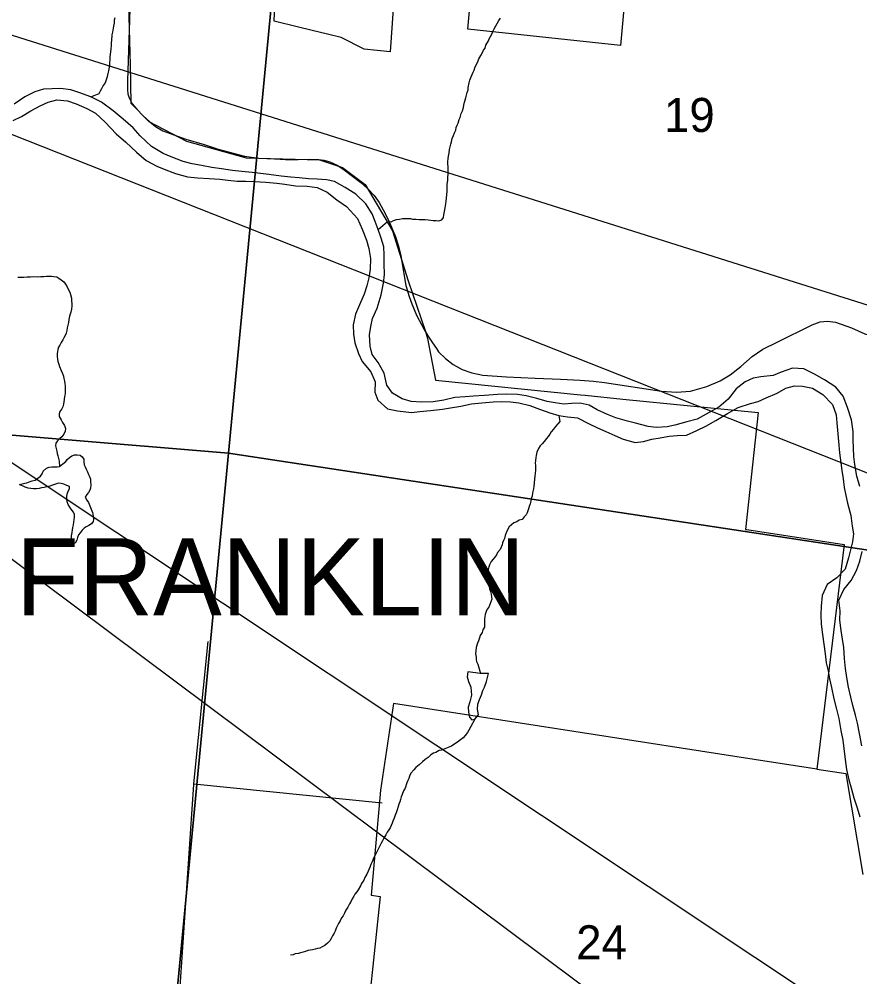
# Model space of a CAD drawing. Extents: x -7.3 to 34, y 0 to 22.
# Drawn here: x 7.321 to 8.354, y 16.227 to 17.405 of the extents above; entities that cross this region are included whole.
import ezdxf

# ---------------------------------------------------------------- set-up
doc = ezdxf.new("R2010")
doc.units = 0
for name, color, linetype in [('GM_X_City_Street', 7, 'Continuous'), ('GM_X_Corporation', 7, 'Continuous'), ('GM_X_Corporation_Text', 7, 'Continuous'), ('GM_X_County_Road', 7, 'Continuous'), ('GM_X_Minor_River', 7, 'Continuous'), ('GM_X_Section_Text', 7, 'Continuous'), ('SH_Text', 7, 'Continuous')]:
    doc.layers.add(name, color=color, linetype=linetype)

msp = doc.modelspace()

# ---------------------------------------------------------------- linework, layer by layer
at = {"layer": 'GM_X_City_Street'}
msp.add_line((7.5353, 16.4644), (7.7668, 16.4414), dxfattribs=at)
msp.add_lwpolyline([(7.515, 16.1606), (7.5352, 16.4637), (7.5353, 16.4644), (7.5529, 16.6394)], dxfattribs=at)
at = {"layer": 'GM_X_Corporation'}
for points in [[(7.6737, 17.8749), (7.5781, 16.8709), (6.5281, 16.9583), (6.6194, 17.9753)], [(8.6893, 17.7371), (8.5942, 16.7168), (7.5781, 16.8709), (7.6737, 17.8749)], [(7.5781, 16.8709), (7.4799, 15.8457), (6.4371, 15.9508), (6.5281, 16.9583)], [(8.5942, 16.7168), (8.4992, 15.7029), (7.4799, 15.8457), (7.5781, 16.8709)]]:
    msp.add_lwpolyline(points, close=True, dxfattribs=at)
for points in [[(8.0931, 17.7385), (8.0598, 17.3723), (7.8722, 17.3924), (7.8829, 17.5093)], [(7.7823, 17.4468), (7.7791, 17.3996), (7.7767, 17.3644), (7.7446, 17.3678), (7.7163, 17.382), (7.6995, 17.3861), (7.6809, 17.3907), (7.6622, 17.3953), (7.6357, 17.4018), (7.634, 17.4022), (7.6362, 17.4532)], [(7.4551, 17.4222), (7.4572, 17.3486), (7.4578, 17.3014), (7.48, 17.279), (7.5265, 17.2546), (7.5995, 17.2342), (7.6897, 17.2318), (7.7181, 17.2223), (7.7461, 17.2012), (7.7794, 17.1442), (7.7987, 17.083), (7.8202, 17.0207), (7.8227, 17.0119), (7.8326, 16.9608), (8.0108, 16.9429), (8.0165, 16.9423), (8.0629, 16.9376), (8.229, 16.921), (8.2137, 16.7774), (8.215, 16.7772), (8.3348, 16.7587), (8.3013, 16.4827), (8.2244, 16.4945), (7.7807, 16.5633), (7.765, 16.4567), (7.7642, 16.4475), (7.7533, 16.3279), (7.7646, 16.3262), (7.7435, 16.1277)], [(7.4551, 17.4222), (7.4572, 17.3486), (7.4578, 17.3014), (7.48, 17.279), (7.5265, 17.2546), (7.5995, 17.2342), (7.6897, 17.2318), (7.7181, 17.2223), (7.7461, 17.2012), (7.7795, 17.1442), (7.7987, 17.083), (7.8202, 17.0207), (7.8227, 17.0119), (7.8326, 16.9608), (8.0108, 16.9429), (8.0165, 16.9423), (8.0629, 16.9376), (8.229, 16.921), (8.2137, 16.7774), (8.215, 16.7772), (8.3348, 16.7587), (8.3013, 16.4827), (8.3368, 16.4772), (8.3577, 16.3531)]]:
    msp.add_lwpolyline(points, dxfattribs=at)
at = {"layer": 'GM_X_County_Road'}
for points in [[(7.4566, 17.4171), (7.4564, 17.4038), (7.4536, 17.3288), (7.4537, 17.3178), (7.454, 17.313), (7.4557, 17.3078), (7.4597, 17.3006), (7.4652, 17.2941), (7.473, 17.2859), (7.4813, 17.2785), (7.4882, 17.2728), (7.4971, 17.2675), (7.5254, 17.2571), (7.5481, 17.2505), (7.5652, 17.2448), (7.5976, 17.2363), (7.6151, 17.2338), (7.6344, 17.2329), (7.6479, 17.2322), (7.6638, 17.2321), (7.6771, 17.2325), (7.6889, 17.2321), (7.6953, 17.2313), (7.7027, 17.2292), (7.7123, 17.2248), (7.7202, 17.2194), (7.7406, 17.2039), (7.7489, 17.1966), (7.7569, 17.1879), (7.763, 17.1791), (7.768, 17.1703), (7.7742, 17.1584), (7.7782, 17.1491), (7.7834, 17.1371), (7.787, 17.1257), (7.7897, 17.1138), (7.796, 17.0772), (7.7999, 17.0638), (7.8032, 17.0548), (7.8091, 17.0409), (7.8184, 17.0232), (7.8232, 17.0153), (7.8288, 17.0069), (7.8336, 16.9997)], [(8.2525, 17.0076), (8.2956, 17.0288), (8.3054, 17.0324), (8.3142, 17.0333), (8.3241, 17.0322), (8.3437, 17.0253), (8.3601, 17.0176), (8.3853, 17.0105), (8.4431, 17.003), (8.4875, 16.9979), (8.5306, 16.9929), (8.5866, 16.9859), (8.594, 16.9857), (8.6023, 16.9868), (8.613, 16.9901), (8.6204, 16.994)], [(7.8336, 16.9997), (7.8363, 16.9958), (7.8448, 16.9875), (7.8541, 16.9799), (7.8652, 16.9738), (7.8773, 16.9697), (7.8905, 16.9669), (7.9197, 16.965), (7.9548, 16.9633), (7.9861, 16.9622), (8.0102, 16.961), (8.0267, 16.9595), (8.04, 16.958), (8.1102, 16.9473), (8.1286, 16.9461), (8.146, 16.9474), (8.1662, 16.9532), (8.1823, 16.96), (8.1947, 16.9673), (8.2077, 16.9777), (8.2217, 16.9898), (8.2349, 16.9989), (8.2525, 17.0076)]]:
    msp.add_lwpolyline(points, dxfattribs=at)
at = {"layer": 'GM_X_Minor_River'}
for points in [[(7.4088, 17.309), (7.4168, 17.3123), (7.4191, 17.3133), (7.4207, 17.3163), (7.4223, 17.3193), (7.4239, 17.3227), (7.4258, 17.3253), (7.427, 17.3279), (7.4278, 17.3306), (7.4291, 17.334), (7.4299, 17.3378), (7.4307, 17.3412), (7.4316, 17.3457), (7.432, 17.3484), (7.4321, 17.3518), (7.4325, 17.3544), (7.4326, 17.3582), (7.4331, 17.3643), (7.4336, 17.3681), (7.4341, 17.3723), (7.4341, 17.3753), (7.4346, 17.3783), (7.4351, 17.3852), (7.4356, 17.3886), (7.4369, 17.3961), (7.4377, 17.3995), (7.4378, 17.4037), (7.4386, 17.4068)], [(7.7618, 17.1462), (7.7734, 17.1558), (7.7779, 17.1555), (7.7806, 17.1572), (7.7844, 17.1582), (7.7882, 17.1589), (7.792, 17.1596), (7.7955, 17.1595), (7.7981, 17.1594), (7.8015, 17.1594), (7.8042, 17.1589), (7.8083, 17.1588), (7.8125, 17.1584), (7.8159, 17.1583), (7.8197, 17.1582), (7.8235, 17.1578), (7.8265, 17.1577), (7.8295, 17.1572), (7.8333, 17.1572), (7.8367, 17.1567), (7.8402, 17.1578), (7.8421, 17.1608), (7.8426, 17.1642), (7.8434, 17.168), (7.8443, 17.1725), (7.8452, 17.1774), (7.8456, 17.1808), (7.8461, 17.1846), (7.8462, 17.1892), (7.8466, 17.1926), (7.8467, 17.1975), (7.8468, 17.2013), (7.8477, 17.2066), (7.8478, 17.2104), (7.8479, 17.2142), (7.8479, 17.2173), (7.848, 17.2203), (7.8481, 17.2234), (7.8477, 17.2264), (7.8478, 17.2294), (7.8479, 17.2332), (7.8483, 17.2363), (7.8492, 17.2397), (7.8496, 17.2442), (7.8513, 17.251), (7.8521, 17.2537), (7.853, 17.2578), (7.8546, 17.2616), (7.8558, 17.265), (7.8574, 17.268), (7.8578, 17.2714), (7.859, 17.2741), (7.8602, 17.2767), (7.8614, 17.2812), (7.8626, 17.2839), (7.8639, 17.2888), (7.8655, 17.2918), (7.8667, 17.2959), (7.8671, 17.299), (7.868, 17.3024), (7.8696, 17.3077), (7.8704, 17.3111), (7.8713, 17.3145), (7.8725, 17.3179), (7.8725, 17.3205), (7.8738, 17.3262), (7.8746, 17.3296), (7.8762, 17.3337), (7.8786, 17.3394), (7.8798, 17.342), (7.8814, 17.3462), (7.8834, 17.3495), (7.885, 17.3533), (7.8858, 17.356), (7.8882, 17.3601), (7.8902, 17.3635), (7.8914, 17.3665), (7.8933, 17.3691), (7.8945, 17.3725), (7.8977, 17.3778), (7.8985, 17.3804), (7.9001, 17.3834), (7.902, 17.3868), (7.9029, 17.3894), (7.9045, 17.3928), (7.9068, 17.3962), (7.9084, 17.3992), (7.9104, 17.4029), (7.9123, 17.4059)], [(7.7608, 17.0494), (7.7658, 17.0659), (7.7684, 17.0799), (7.7698, 17.0909), (7.7694, 17.1038), (7.7693, 17.1149), (7.7688, 17.1247), (7.7657, 17.1355), (7.7618, 17.1462), (7.7583, 17.1558), (7.7547, 17.1654), (7.7467, 17.1777), (7.7345, 17.1894), (7.7214, 17.1977), (7.7084, 17.2049), (7.6986, 17.207), (7.6868, 17.2077), (7.6762, 17.2084), (7.6649, 17.2094), (7.6547, 17.2104), (7.6429, 17.2115), (7.6274, 17.2138), (7.6172, 17.2148), (7.607, 17.2162), (7.5945, 17.2173), (7.5828, 17.2187), (7.5692, 17.2206), (7.5575, 17.2224), (7.5447, 17.2246), (7.5334, 17.2268), (7.5224, 17.2297), (7.5074, 17.2354), (7.4977, 17.2395), (7.4831, 17.2482), (7.4694, 17.2611), (7.4606, 17.2712), (7.4483, 17.2817), (7.4361, 17.2919), (7.4219, 17.3025), (7.4088, 17.309), (7.3938, 17.3143), (7.384, 17.3176), (7.3716, 17.3194), (7.3613, 17.3189), (7.3507, 17.3184), (7.34, 17.3153), (7.3277, 17.3091), (7.3146, 17.2999)], [(7.3133, 17.2802), (7.3233, 17.2849), (7.3348, 17.2918), (7.3464, 17.298), (7.3563, 17.3027), (7.367, 17.3055), (7.3799, 17.3044), (7.3908, 17.3007), (7.4039, 17.2946), (7.4144, 17.2891), (7.4262, 17.2781), (7.4399, 17.2637), (7.4518, 17.2535), (7.4647, 17.2411), (7.4766, 17.2309), (7.49, 17.2237), (7.5009, 17.2193), (7.5126, 17.2148), (7.5276, 17.2106), (7.5397, 17.2095), (7.5541, 17.2088), (7.5674, 17.2077), (7.5772, 17.2067), (7.5885, 17.2056), (7.5992, 17.2054), (7.6098, 17.2051), (7.6238, 17.2044), (7.6374, 17.2029), (7.6472, 17.2019), (7.6604, 17.1996), (7.6745, 17.1993), (7.6869, 17.1978), (7.6993, 17.1918), (7.7112, 17.1824), (7.7231, 17.1741), (7.7367, 17.1594), (7.7421, 17.1463), (7.7474, 17.1329), (7.7506, 17.1225), (7.7525, 17.1103), (7.7522, 17.0971), (7.7504, 17.0865), (7.7482, 17.0766), (7.7449, 17.0665), (7.7401, 17.0563), (7.7341, 17.0421), (7.7311, 17.0288), (7.7315, 17.0174), (7.7331, 17.0068), (7.7377, 16.9937), (7.7424, 16.9837), (7.7531, 16.9709), (7.7581, 16.9587), (7.7577, 16.9461), (7.7616, 16.9362), (7.7735, 16.9256), (7.7856, 16.923), (7.803, 16.9211), (7.8132, 16.9223), (7.8262, 16.9235), (7.841, 16.925), (7.8509, 16.9267), (7.8635, 16.929), (7.8768, 16.9317), (7.8894, 16.9329), (7.9034, 16.9341), (7.9133, 16.9346), (7.9247, 16.9343), (7.9349, 16.9329), (7.9484, 16.9295), (7.9601, 16.9251), (7.9728, 16.9206), (7.9841, 16.9172), (7.9947, 16.9158), (8.0072, 16.9144), (8.0207, 16.9076), (8.0315, 16.9024), (8.042, 16.8976), (8.0529, 16.8927), (8.063, 16.8883), (8.0777, 16.8841), (8.0883, 16.8854), (8.0983, 16.8882), (8.1085, 16.8898), (8.1196, 16.8918), (8.1295, 16.8927), (8.1409, 16.8932), (8.1539, 16.8989), (8.1647, 16.9043), (8.177, 16.9112), (8.1916, 16.92), (8.2047, 16.9273)], [(7.319, 17.0874), (7.322, 17.0873), (7.3262, 17.0876), (7.3304, 17.0879), (7.3346, 17.0878), (7.3388, 17.0881), (7.3429, 17.088), (7.3471, 17.0883), (7.3509, 17.0882), (7.3543, 17.0885), (7.3577, 17.0888), (7.3604, 17.0888), (7.3634, 17.0883), (7.3668, 17.0879), (7.3694, 17.0863), (7.3724, 17.084), (7.3754, 17.0816), (7.3776, 17.0789), (7.3794, 17.0754), (7.3809, 17.0727), (7.3827, 17.0689), (7.3838, 17.0662), (7.3848, 17.0616), (7.3851, 17.0582), (7.3854, 17.0548), (7.3854, 17.0521), (7.3849, 17.048), (7.3841, 17.0446), (7.3833, 17.0419), (7.3825, 17.0393), (7.3816, 17.0355), (7.3811, 17.0317), (7.3803, 17.0283), (7.3795, 17.0253), (7.379, 17.0219), (7.3782, 17.0185), (7.377, 17.0158), (7.3754, 17.0128), (7.3742, 17.0102), (7.3723, 17.0072), (7.3707, 17.0038), (7.3691, 17.0012), (7.3683, 16.9985), (7.3679, 16.9959), (7.3674, 16.9932), (7.3673, 16.9898), (7.3677, 16.9868), (7.3683, 16.9837), (7.3694, 16.9803), (7.3701, 16.9776), (7.3723, 16.9726), (7.3737, 16.9691), (7.3752, 16.9657), (7.3755, 16.963), (7.3765, 16.9596), (7.3769, 16.9569), (7.3772, 16.9535), (7.3771, 16.9501), (7.377, 16.9467), (7.377, 16.944), (7.3765, 16.9406), (7.3761, 16.9372), (7.3756, 16.9341), (7.3752, 16.9315)], [(8.3542, 16.8301), (8.3504, 16.8427), (8.3481, 16.8572), (8.3469, 16.8671), (8.3464, 16.8774), (8.3459, 16.8876), (8.3458, 16.8979), (8.3439, 16.912), (8.3389, 16.9273), (8.3336, 16.9411), (8.3244, 16.9523), (8.3106, 16.9614), (8.2983, 16.9682), (8.2852, 16.9746), (8.2712, 16.9757), (8.2574, 16.9707), (8.2474, 16.9664), (8.2326, 16.9649), (8.2231, 16.9632), (8.2131, 16.9589), (8.2019, 16.9501), (8.1921, 16.9374), (8.1808, 16.9275), (8.1689, 16.9209), (8.1543, 16.913), (8.1413, 16.9095), (8.1268, 16.9053), (8.1172, 16.9036), (8.1039, 16.9025), (8.0937, 16.9039), (8.0783, 16.908), (8.0685, 16.9106), (8.0542, 16.9147), (8.0437, 16.9184), (8.0313, 16.9244), (8.0212, 16.93), (8.0103, 16.9325), (7.9997, 16.932), (7.9902, 16.9315), (7.9796, 16.9329), (7.9698, 16.9347), (7.957, 16.9381), (7.9438, 16.9414), (7.9332, 16.9432), (7.9203, 16.9435), (7.9086, 16.9431), (7.8926, 16.942), (7.879, 16.9412), (7.8687, 16.9403), (7.8562, 16.9395), (7.8428, 16.9364), (7.8295, 16.9341), (7.8154, 16.9337), (7.8026, 16.9347), (7.7916, 16.9377), (7.7797, 16.9448), (7.7727, 16.9545), (7.7693, 16.9694), (7.7621, 16.9825), (7.7544, 16.9925), (7.752, 17.0025), (7.7512, 17.0166), (7.753, 17.0268), (7.7548, 17.0366), (7.7608, 17.0494)], [(8.2047, 16.9273), (8.2196, 16.9322), (8.2292, 16.9346), (8.2391, 16.9389), (8.2526, 16.945), (8.263, 16.9509), (8.2737, 16.954), (8.2835, 16.9534), (8.2959, 16.9508), (8.3086, 16.9432), (8.3205, 16.9308), (8.3251, 16.9181), (8.3259, 16.9082), (8.3271, 16.8949), (8.328, 16.8854), (8.3291, 16.8713), (8.3307, 16.8591), (8.332, 16.8496), (8.3336, 16.8397), (8.3349, 16.829), (8.3369, 16.8191), (8.3389, 16.8096), (8.3431, 16.7946), (8.3446, 16.7813), (8.3463, 16.7718), (8.3452, 16.7619), (8.3427, 16.7521), (8.3402, 16.7423), (8.336, 16.7284), (8.3259, 16.718), (8.3139, 16.7096), (8.3079, 16.696), (8.3064, 16.6828), (8.3061, 16.6725), (8.3066, 16.6608), (8.3082, 16.6482), (8.3097, 16.6364), (8.3113, 16.6242), (8.3129, 16.6135), (8.315, 16.6036), (8.317, 16.5937), (8.3193, 16.583), (8.322, 16.5692), (8.3255, 16.5562), (8.3282, 16.5448), (8.3309, 16.5303), (8.3332, 16.5181), (8.3345, 16.5082), (8.336, 16.4945), (8.3379, 16.4823), (8.3406, 16.4693), (8.3434, 16.4597), (8.3469, 16.4475), (8.3507, 16.4349), (8.3542, 16.4238)], [(7.3752, 16.9315), (7.3743, 16.9281), (7.3731, 16.9255), (7.3704, 16.9221), (7.3696, 16.9195), (7.3699, 16.916), (7.3721, 16.9122), (7.3739, 16.9087), (7.3765, 16.9052), (7.3776, 16.9014), (7.3771, 16.898), (7.3755, 16.8946), (7.3732, 16.8913), (7.3705, 16.889), (7.3677, 16.8864), (7.3658, 16.8834), (7.3653, 16.88), (7.366, 16.8766), (7.3667, 16.8735), (7.3674, 16.8705), (7.3681, 16.8678), (7.3688, 16.8644), (7.3699, 16.8613), (7.3701, 16.8545)], [(7.9841, 16.9172), (7.9854, 16.9102), (7.9827, 16.9073), (7.9799, 16.9039), (7.9776, 16.9005), (7.9748, 16.8972), (7.9729, 16.8945), (7.9709, 16.8915), (7.969, 16.8889), (7.9659, 16.8856), (7.9635, 16.8826), (7.9612, 16.88), (7.9592, 16.8766), (7.9569, 16.8725), (7.956, 16.8683), (7.9556, 16.8657), (7.9555, 16.8622), (7.9551, 16.8588), (7.9554, 16.8562), (7.9553, 16.8527), (7.9552, 16.8497), (7.9548, 16.8463), (7.9547, 16.8425), (7.9542, 16.8395), (7.9538, 16.8342), (7.9533, 16.8307), (7.9528, 16.8273), (7.9516, 16.8224), (7.9511, 16.8183), (7.9499, 16.8152), (7.9495, 16.8122), (7.9487, 16.8088), (7.9474, 16.8054), (7.9466, 16.8028), (7.945, 16.7979), (7.9438, 16.7952), (7.9415, 16.7926), (7.9388, 16.7896), (7.9353, 16.7886), (7.9326, 16.7867), (7.9288, 16.7853), (7.9257, 16.7831), (7.923, 16.7805), (7.9206, 16.776), (7.9194, 16.7733), (7.9182, 16.77), (7.9174, 16.7662), (7.9162, 16.7635), (7.915, 16.7609), (7.9142, 16.7583), (7.913, 16.7556), (7.9118, 16.7526), (7.9087, 16.7489), (7.9075, 16.7462), (7.9055, 16.7432), (7.9032, 16.7406), (7.9008, 16.738), (7.8989, 16.7339), (7.898, 16.7312), (7.8972, 16.7282), (7.8968, 16.7252), (7.8967, 16.7214), (7.8966, 16.718), (7.8969, 16.7138), (7.8976, 16.7096), (7.8983, 16.7069), (7.899, 16.7043), (7.9, 16.7012), (7.9007, 16.6978), (7.9014, 16.6943), (7.9017, 16.6917), (7.9005, 16.6883), (7.8993, 16.6849), (7.8981, 16.6819), (7.8961, 16.6792), (7.8946, 16.6766), (7.8933, 16.6728), (7.8929, 16.6702), (7.8925, 16.6668), (7.8928, 16.663), (7.8927, 16.6603), (7.8926, 16.6573), (7.8907, 16.6539), (7.8898, 16.6505), (7.8875, 16.6471), (7.8867, 16.6441), (7.8851, 16.6403), (7.8839, 16.6373), (7.8826, 16.632), (7.8821, 16.6279), (7.8817, 16.6245), (7.8823, 16.6203), (7.8823, 16.6176), (7.883, 16.6149), (7.8844, 16.6115), (7.8855, 16.6088), (7.8876, 16.6004)], [(7.3211, 16.8327), (7.3241, 16.8334), (7.3275, 16.8341), (7.3302, 16.8348), (7.334, 16.8362), (7.3367, 16.8369), (7.3401, 16.838), (7.3436, 16.8402), (7.3467, 16.8428), (7.349, 16.8458), (7.3502, 16.8488), (7.3541, 16.8525), (7.3576, 16.854), (7.3606, 16.8543), (7.364, 16.8542), (7.3674, 16.8541), (7.3701, 16.8545), (7.3743, 16.8578), (7.3778, 16.8607), (7.3794, 16.8634), (7.3825, 16.8656), (7.3852, 16.8678), (7.3886, 16.8689), (7.392, 16.8692), (7.3954, 16.8687), (7.398, 16.8664), (7.3999, 16.8637), (7.4002, 16.8603), (7.4005, 16.8568), (7.4016, 16.8541), (7.403, 16.8515), (7.4048, 16.848), (7.4059, 16.8449), (7.407, 16.8423), (7.4081, 16.8392), (7.4084, 16.8361), (7.4087, 16.832), (7.4082, 16.8282), (7.4074, 16.8255), (7.4058, 16.8229), (7.4039, 16.8203), (7.4019, 16.8169), (7.4037, 16.8131), (7.4059, 16.8104), (7.4107, 16.798)], [(7.4107, 16.798), (7.4113, 16.7966), (7.4116, 16.7931), (7.4119, 16.7897), (7.4115, 16.7871), (7.4095, 16.7841), (7.4064, 16.7822), (7.403, 16.7804), (7.4003, 16.7789), (7.398, 16.7763), (7.3956, 16.7733), (7.3937, 16.7707), (7.3925, 16.7673), (7.3913, 16.7643), (7.3893, 16.7606), (7.3866, 16.7602), (7.3852, 16.7633), (7.3849, 16.7664), (7.3849, 16.7694), (7.3858, 16.7736), (7.3862, 16.777), (7.3867, 16.7796), (7.3875, 16.783), (7.388, 16.7864), (7.3884, 16.7895), (7.3888, 16.7921), (7.3885, 16.7955), (7.3875, 16.7986), (7.3845, 16.8021), (7.3827, 16.8048), (7.3808, 16.8079), (7.3798, 16.8113), (7.3791, 16.8147), (7.3792, 16.8178), (7.3796, 16.8208), (7.3808, 16.8242), (7.3824, 16.8272), (7.3824, 16.8299), (7.3791, 16.8315), (7.3757, 16.8331), (7.3723, 16.8339), (7.3685, 16.834), (7.3651, 16.8329), (7.3616, 16.8318), (7.3582, 16.8304), (7.3548, 16.8297), (7.3513, 16.829), (7.3479, 16.8283), (7.3452, 16.8276), (7.3418, 16.8273), (7.3384, 16.8274), (7.335, 16.8275), (7.3316, 16.8279), (7.3278, 16.8292), (7.3211, 16.8327)], [(8.3565, 16.5114), (8.3539, 16.5263), (8.3512, 16.5393), (8.3488, 16.5488), (8.3457, 16.561), (8.3429, 16.571), (8.3402, 16.5832), (8.3382, 16.5954), (8.3363, 16.6065), (8.3354, 16.6186), (8.3343, 16.632), (8.3326, 16.6423), (8.331, 16.6529), (8.3295, 16.6659), (8.3298, 16.6773), (8.3282, 16.6902), (8.3346, 16.7033), (8.3433, 16.7145), (8.35, 16.7269), (8.3541, 16.7385), (8.3571, 16.7502)], [(7.8876, 16.6004), (7.872, 16.6022), (7.8715, 16.5962), (7.8732, 16.5904), (7.8757, 16.5835), (7.8766, 16.5736), (7.8748, 16.5653), (7.8724, 16.5589), (7.873, 16.5528), (7.8743, 16.5467), (7.8769, 16.5432), (7.8807, 16.5439), (7.8854, 16.5495), (7.8841, 16.5564), (7.8846, 16.5624), (7.8867, 16.5684), (7.8891, 16.5741)], [(7.8891, 16.5741), (7.8907, 16.5794), (7.8927, 16.5835), (7.8952, 16.5903), (7.8977, 16.6004), (7.8876, 16.6004)], [(7.8807, 16.5439), (7.8736, 16.5304), (7.8716, 16.5278), (7.8689, 16.524), (7.8665, 16.521), (7.8631, 16.5188), (7.8596, 16.5159), (7.8561, 16.5137), (7.8523, 16.5107), (7.8481, 16.5093), (7.8439, 16.5075), (7.8397, 16.5061), (7.837, 16.5054), (7.8328, 16.5032), (7.8301, 16.5021), (7.8266, 16.5003), (7.8235, 16.4969), (7.8197, 16.4943), (7.8166, 16.4917), (7.8123, 16.488), (7.8081, 16.4847), (7.8057, 16.4817), (7.8022, 16.4776), (7.8006, 16.4738), (7.7995, 16.4712), (7.7983, 16.4686), (7.7971, 16.4656), (7.795, 16.4592), (7.793, 16.4558), (7.7914, 16.4516), (7.7902, 16.4486), (7.7894, 16.4452), (7.7886, 16.4426), (7.7874, 16.4396), (7.7866, 16.4369), (7.7853, 16.4328), (7.7841, 16.429), (7.7829, 16.426), (7.7817, 16.4222), (7.7801, 16.4188), (7.7793, 16.4162), (7.7781, 16.4135), (7.7765, 16.4105), (7.7749, 16.4079), (7.773, 16.4053), (7.7714, 16.4019), (7.769, 16.3978), (7.7671, 16.3944), (7.7655, 16.3918), (7.7635, 16.3876), (7.7615, 16.3835), (7.7599, 16.3801), (7.7583, 16.3767), (7.7568, 16.3741), (7.7547, 16.3685), (7.7528, 16.3655), (7.752, 16.3628), (7.7508, 16.3602), (7.7496, 16.3572), (7.748, 16.3534), (7.7456, 16.3493), (7.7444, 16.3463), (7.7416, 16.3421), (7.7401, 16.3391), (7.7373, 16.3343), (7.7357, 16.3316), (7.7334, 16.329), (7.7322, 16.3264), (7.7298, 16.323), (7.7287, 16.3204), (7.7267, 16.317), (7.7247, 16.3129), (7.7223, 16.3091), (7.7207, 16.3057), (7.7188, 16.3024), (7.7168, 16.2998), (7.7152, 16.296), (7.7133, 16.293), (7.7117, 16.2896), (7.7105, 16.287), (7.7089, 16.2836), (7.7077, 16.281), (7.7057, 16.2776), (7.7041, 16.2746), (7.7026, 16.2716), (7.6998, 16.2686), (7.6964, 16.266), (7.6929, 16.2642), (7.6902, 16.2627), (7.6872, 16.262), (7.6845, 16.2613), (7.6811, 16.2606), (7.6784, 16.2599), (7.6754, 16.2596), (7.6727, 16.2585), (7.6696, 16.2578), (7.6666, 16.2568), (7.6639, 16.2561), (7.6601, 16.2554), (7.6574, 16.2543), (7.654, 16.254)]]:
    msp.add_lwpolyline(points, dxfattribs=at)
at = {"layer": 'SH_Text'}
for points in [[(9.4026, 16.4356), (9.4027, 16.725), (5.7947, 17.8636)], [(9.4026, 15.1778), (9.4027, 15.4673), (5.869, 17.8194)]]:
    msp.add_lwpolyline(points, close=True, dxfattribs=at)

# ---------------------------------------------------------------- texts
at = {"layer": 'GM_X_Corporation_Text'}
msp.add_text('FRANKLIN', height=0.0947, rotation=0, dxfattribs=at).set_placement((7.3164, 16.6716))
at = {"layer": 'GM_X_Section_Text'}
for s, p in [('19', (8.1134, 17.2659)), ('24', (8.0054, 16.2488))]:
    msp.add_text(s, height=0.04186, rotation=0, dxfattribs=at).set_placement(p)

doc.saveas('drawing.dxf')
